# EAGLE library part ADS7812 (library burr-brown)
Low-Power, Serial 12-Bit Sampling ADC
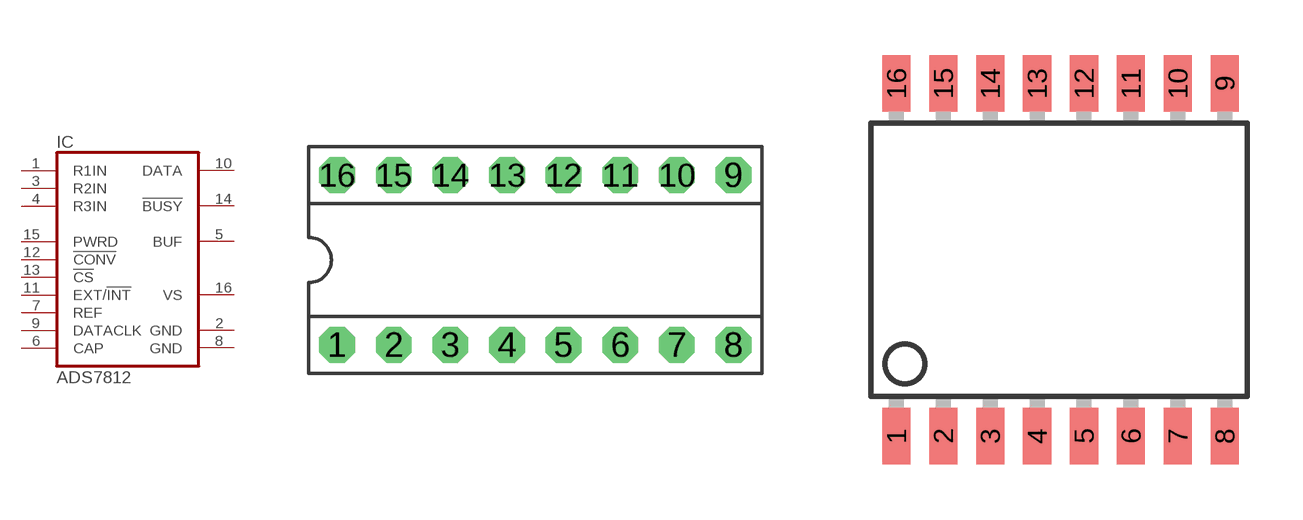
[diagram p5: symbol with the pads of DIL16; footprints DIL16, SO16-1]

Designator prefix IC

## ADS7812P (MF: TEXAS INSTRUMENT CONNECTORS; MPN: ADS7812P; OC_FARNELL: 1509513; OC_NEWARK: 74C7091)  [DIL16]
1  R1IN  in
2  GND  pwr
3  R2IN  in
4  R3IN  in
5  BUF  out
6  CAP  pas
7  REF
8  GND  pwr
9  DATACLK
10  DATA  out
11  EXT/!INT  in
12  !CONV  in
13  !CS  in
14  !BUSY  out
15  PWRD  in
16  VS  pwr

## ADS7812U (MF: TEXAS INSTRUMENT CONNECTORS; MPN: ADS7812U; OC_FARNELL: 1459274; OC_NEWARK: 14M8148)  [SO16-1]
Pads as for DIL16

## Footprint DIL16 (pad centres in mm)
Dual In Line
drill 0.813 pad 1.6 octagon: 1 -8.89,-3.81; 2 -6.35,-3.81; 3 -3.81,-3.81; 4 -1.27,-3.81; 5 1.27,-3.81; 6 3.81,-3.81; 7 6.35,-3.81; 8 8.89,-3.81; 9 8.89,3.81; 10 6.35,3.81; 11 3.81,3.81; 12 1.27,3.81; 13 -1.27,3.81; 14 -3.81,3.81; 15 -6.35,3.81; 16 -8.89,3.81

## Footprint SO16-1 (pad centres in mm)
Small Outline Package
smd 0.762 x 1.524: 1 -4.445,-4.775; 2 -3.175,-4.775; 3 -1.905,-4.775; 4 -0.635,-4.775; 5 0.635,-4.775; 6 1.905,-4.775; 7 3.175,-4.775; 8 4.445,-4.775; 9 4.445,4.775; 10 3.175,4.775; 11 1.905,4.775; 12 0.635,4.775; 13 -0.635,4.775; 14 -1.905,4.775; 15 -3.175,4.775; 16 -4.445,4.775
